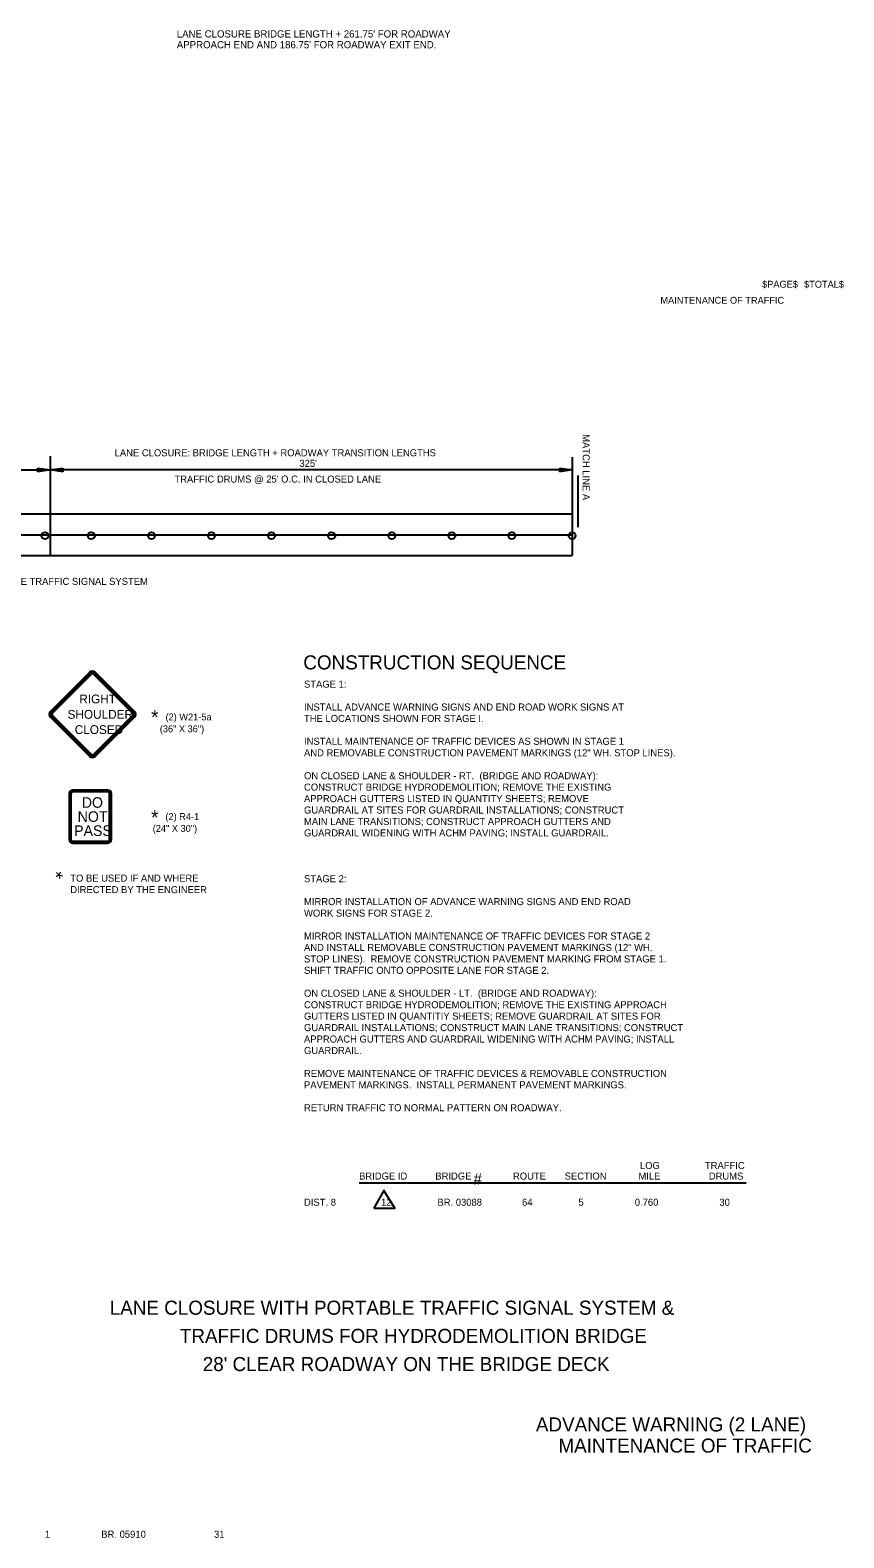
# Model space of a CAD drawing. Extents: x 1930579 to 1934718, y 596452 to 597844.
# Drawn here: x 1933176 to 1933869, y 596560 to 597843 of the extents above; entities that cross this region are included whole.
import ezdxf

# ---------------------------------------------------------------- set-up
doc = ezdxf.new("R2010")
doc.units = 0
for name, color, linetype in [('Default', 7, 'Continuous'), ('P_TC_Signs_Permanent', 7, 'Continuous'), ('P_TC_Signs_Temporary', 7, 'Continuous'), ('R_Annotation', 7, 'Continuous'), ('R_Border', 7, 'Continuous')]:
    doc.layers.add(name, color=color, linetype=linetype)

msp = doc.modelspace()

# ---------------------------------------------------------------- linework, layer by layer
at = {"layer": 'Default'}
for p, q in [((1933193.1, 597480.5), (1933193.1, 597418.7)), ((1933637.5, 597479.8), (1933637.5, 597395.9)), ((1933119.2, 597468.9), (1933193.1, 597468.9)), ((1933182.6, 597467.4), (1933182.6, 597470.5)), ((1933182.6, 597470.5), (1933193.1, 597468.9)), ((1933193.1, 597468.9), (1933182.6, 597467.4)), ((1933193.1, 597468.9), (1933203.7, 597470.5)), ((1933203.7, 597467.4), (1933193.1, 597468.9)), ((1933637.5, 597468.9), (1933193.1, 597468.9)), ((1933203.7, 597470.5), (1933203.7, 597467.4)), ((1933627, 597467.4), (1933627, 597470.5)), ((1933627, 597470.5), (1933637.5, 597468.9)), ((1933637.5, 597468.9), (1933627, 597467.4)), ((1933642.2, 597464.1), (1933642.2, 597420.1)), ((1933193.1, 597447.9), (1933193.1, 597395.6)), ((1932535.5, 597431.5), (1933637.5, 597431.5)), ((1932443.4, 597413.7), (1933637.5, 597413.7)), ((1932535.5, 597395.9), (1933637.5, 597395.9))]:
    msp.add_line(p, q, dxfattribs=at)
for centre in [(1933188.6, 597412.9), (1933228, 597412.9), (1933279.2, 597412.9), (1933330.3, 597412.9), (1933381.5, 597412.9), (1933432.6, 597412.9), (1933483.8, 597412.9), (1933535, 597412.9), (1933586.1, 597412.9), (1933637.3, 597412.9)]:
    msp.add_circle(centre, 2.88, dxfattribs=at)
at = {"layer": 'P_TC_Signs_Permanent'}
for p, q in [((1933242.1, 597196.2), (1933212.1, 597196.2)), ((1933209.1, 597193.2), (1933209.1, 597154.2)), ((1933209.7, 597193.2), (1933209.7, 597154.2)), ((1933210.6, 597193.2), (1933210.6, 597154.2)), ((1933242.1, 597195.6), (1933212.1, 597195.6)), ((1933242.1, 597194.7), (1933212.1, 597194.7)), ((1933243.6, 597154.2), (1933243.6, 597193.2)), ((1933244.5, 597154.2), (1933244.5, 597193.2)), ((1933245.1, 597154.2), (1933245.1, 597193.2)), ((1933212.1, 597152.7), (1933242.1, 597152.7)), ((1933212.1, 597151.8), (1933242.1, 597151.8)), ((1933212.1, 597151.2), (1933242.1, 597151.2))]:
    msp.add_line(p, q, dxfattribs=at)
for centre, radius, start, end in [((1933212.1, 597193.2), 3, 90, 180), ((1933242.1, 597193.2), 3, 360, 90), ((1933212.1, 597193.2), 2.4, 90, 180), ((1933212.1, 597193.2), 1.5, 90, 180), ((1933242.1, 597193.2), 2.4, 360, 90), ((1933242.1, 597193.2), 1.5, 360, 90), ((1933212.1, 597154.2), 3, 180, 270), ((1933212.1, 597154.2), 2.4, 180, 270), ((1933212.1, 597154.2), 1.5, 180, 270), ((1933242.1, 597154.2), 3, 270, 360), ((1933242.1, 597154.2), 2.4, 270, 360), ((1933242.1, 597154.2), 1.5, 270, 360)]:
    msp.add_arc(centre, radius, start, end, dxfattribs=at)
at = {"layer": 'P_TC_Signs_Temporary'}
for p, q in [((1933193.2, 597263.1), (1933226.7, 597296.6)), ((1933193.9, 597262.5), (1933227.3, 597295.9)), ((1933194.8, 597261.6), (1933228.2, 597295)), ((1933229.8, 597295), (1933263.3, 597261.6)), ((1933230.8, 597295.9), (1933264.2, 597262.5)), ((1933231.4, 597296.6), (1933264.8, 597263.1)), ((1933226.7, 597225), (1933193.2, 597258.4)), ((1933227.3, 597225.6), (1933193.9, 597259)), ((1933228.2, 597226.5), (1933194.8, 597260)), ((1933263.3, 597260), (1933229.8, 597226.5)), ((1933264.2, 597259), (1933230.8, 597225.6)), ((1933264.8, 597258.4), (1933231.4, 597225))]:
    msp.add_line(p, q, dxfattribs=at)
for centre, radius, start, end in [((1933229, 597294.2), 3.38, 45, 135), ((1933229, 597294.2), 2.44, 45, 135), ((1933229, 597294.2), 1.13, 45, 135), ((1933195.6, 597260.8), 3.37, 135, 225), ((1933195.6, 597260.8), 2.44, 135, 225), ((1933195.6, 597260.8), 1.12, 135, 225), ((1933262.5, 597260.8), 1.12, 315, 45), ((1933262.5, 597260.8), 2.44, 315, 45), ((1933262.5, 597260.8), 3.37, 315, 45), ((1933229, 597227.3), 3.38, 225, 315), ((1933229, 597227.3), 2.44, 225, 315), ((1933229, 597227.3), 1.13, 225, 315)]:
    msp.add_arc(centre, radius, start, end, dxfattribs=at)
at = {"layer": 'R_Annotation'}
msp.add_line((1933456, 596861.9), (1933785.4, 596861.9), dxfattribs=at)
msp.add_lwpolyline([(1933468.5, 596840.3), (1933486.5, 596840.3), (1933477.1, 596855.2)], close=True, dxfattribs=at)

# ---------------------------------------------------------------- texts
at = {"layer": 'Default'}
for s, height, rotation, p in [("LANE CLOSURE BRIDGE LENGTH + 261.75' FOR ROADWAY ", 6.14, 360, (1933300.8, 597837.1)), ("APPROACH END AND 186.75' FOR ROADWAY EXIT END.", 6.14, 360, (1933300.8, 597827.9)), ('MATCH LINE A', 6, 270, (1933646.3, 597499.3)), ('LANE CLOSURE: BRIDGE LENGTH + ROADWAY TRANSITION LENGTHS', 6, 360, (1933247.9, 597480.5)), ("325'", 6, 360, (1933405.2, 597471.5)), ("TRAFFIC DRUMS @ 25' O.C. IN CLOSED LANE", 6, 360, (1933298.8, 597458.1)), ('PORTABLE TRAFFIC SIGNAL SYSTEM', 6, 360, (1933130.4, 597371)), ('LANE CLOSURE WITH PORTABLE TRAFFIC SIGNAL SYSTEM &', 12, 360, (1933243.7, 596749.5)), ('TRAFFIC DRUMS FOR HYDRODEMOLITION BRIDGE', 12, 360, (1933303.4, 596725.5)), ("28' CLEAR ROADWAY ON THE BRIDGE DECK", 12, 360, (1933322.9, 596701.5))]:
    msp.add_text(s, height=height, rotation=rotation, dxfattribs=at).set_placement(p)
at = {"layer": 'P_TC_Signs_Permanent'}
for s, rotation, p in [('DO', 360, (1933219.9, 597181.2)), ('NOT', 359.9596, (1933216.4, 597169.2)), ('PASS', 360, (1933213.4, 597157.2))]:
    msp.add_text(s, height=9, rotation=rotation, dxfattribs=at).set_placement(p)
at = {"layer": 'P_TC_Signs_Temporary'}
for s, p in [('RIGHT', (1933217.8, 597270.1)), ('SHOULDER', (1933207.8, 597257)), ('CLOSED', (1933213.9, 597244))]:
    msp.add_text(s, height=7.5, rotation=360, dxfattribs=at).set_placement(p)
at = {"layer": 'R_Annotation'}
for s, height, rotation, p in [('CONSTRUCTION SEQUENCE', 12, 360, (1933408.5, 597299)), ('STAGE 1:', 6, 360, (1933409.1, 597283.5)), ('(2) W21-5a', 5.86, 360, (1933291.2, 597255.6)), ('THE LOCATIONS SHOWN FOR STAGE I.  ', 6, 360, (1933409.1, 597254.3)), ('INSTALL ADVANCE WARNING SIGNS AND END ROAD WORK SIGNS AT', 6, 360, (1933409.1, 597264)), ('(36" X 36")', 5.863, 360, (1933286.3, 597245.5)), ('INSTALL MAINTENANCE OF TRAFFIC DEVICES AS SHOWN IN STAGE 1', 6, 360, (1933409.1, 597234.8)), ('AND REMOVABLE CONSTRUCTION PAVEMENT MARKINGS (12" WH. STOP LINES). ', 6, 360, (1933409.1, 597225)), ('ON CLOSED LANE & SHOULDER - RT.  (BRIDGE AND ROADWAY):', 6, 360, (1933409.1, 597205.5)), ('CONSTRUCT BRIDGE HYDRODEMOLITION; REMOVE THE EXISTING', 6, 360, (1933409.1, 597195.8)), ('APPROACH GUTTERS LISTED IN QUANTITY SHEETS; REMOVE', 6, 360, (1933409.1, 597186)), ('(2) R4-1', 5.86, 360, (1933291.1, 597170.8)), ('GUARDRAIL AT SITES FOR GUARDRAIL INSTALLATIONS; CONSTRUCT', 6, 360, (1933409.1, 597176.3)), ('MAIN LANE TRANSITIONS; CONSTRUCT APPROACH GUTTERS AND', 6, 360, (1933409.1, 597166.5)), ('(24" X 30")', 5.863, 360, (1933280.3, 597160.7)), ('GUARDRAIL WIDENING WITH ACHM PAVING; INSTALL GUARDRAIL. ', 6, 360, (1933409.1, 597156.8)), ('*', 12, 45, (1933204.6, 597115.4)), ('TO BE USED IF AND WHERE', 6, 360, (1933210.1, 597118.3)), ('STAGE 2:', 6, 360, (1933409.1, 597117.8)), ('DIRECTED BY THE ENGINEER', 6, 360, (1933210.1, 597108.5)), ('WORK SIGNS FOR STAGE 2.  ', 6, 360, (1933409.1, 597088.5)), ('MIRROR INSTALLATION OF ADVANCE WARNING SIGNS AND END ROAD', 6, 360, (1933409.1, 597098.3)), ('MIRROR INSTALLATION MAINTENANCE OF TRAFFIC DEVICES FOR STAGE 2', 6, 360, (1933409.1, 597069)), ('AND INSTALL REMOVABLE CONSTRUCTION PAVEMENT MARKINGS (12" WH. ', 6, 360, (1933409.1, 597059.3)), ('STOP LINES).  REMOVE CONSTRUCTION PAVEMENT MARKING FROM STAGE 1.', 6, 360, (1933409.1, 597049.5)), ('SHIFT TRAFFIC ONTO OPPOSITE LANE FOR STAGE 2.', 6, 360, (1933409.1, 597039.8)), ('ON CLOSED LANE & SHOULDER - LT.  (BRIDGE AND ROADWAY):', 6, 360, (1933409.1, 597020.3)), ('CONSTRUCT BRIDGE HYDRODEMOLITION; REMOVE THE EXISTING APPROACH', 6, 360, (1933409.1, 597010.5)), ('GUTTERS LISTED IN QUANTITIY SHEETS; REMOVE GUARDRAIL AT SITES FOR', 6, 360, (1933409.1, 597000.8)), ('GUARDRAIL INSTALLATIONS; CONSTRUCT MAIN LANE TRANSITIONS; CONSTRUCT', 6, 360, (1933409.1, 596991)), ('APPROACH GUTTERS AND GUARDRAIL WIDENING WITH ACHM PAVING; INSTALL', 6, 360, (1933409.1, 596981.3)), ('GUARDRAIL.', 6, 360, (1933409.1, 596971.5)), ('REMOVE MAINTENANCE OF TRAFFIC DEVICES & REMOVABLE CONSTRUCTION', 6, 360, (1933409.1, 596952)), ('PAVEMENT MARKINGS.  INSTALL PERMANENT PAVEMENT MARKINGS.', 6, 360, (1933409.1, 596942.3)), ('RETURN TRAFFIC TO NORMAL PATTERN ON ROADWAY. ', 6, 360, (1933409.1, 596922.8)), ('LOG', 6, 360, (1933695.1, 596873.6)), ('TRAFFIC', 6, 360, (1933750.4, 596873.6)), ('BRIDGE ID', 6, 360, (1933456, 596864.6)), ('BRIDGE ', 6, 360, (1933520.9, 596864.6)), ('#', 9.6, 360, (1933553.4, 596860.4)), ('ROUTE', 6, 360, (1933587, 596864.6)), ('SECTION', 6, 360, (1933631, 596864.6)), ('MILE', 6, 360, (1933693.8, 596864.6)), ('DRUMS', 6, 360, (1933753.7, 596864.6)), ('DIST. 8', 6, 360, (1933409.1, 596842.3)), ('12', 6, 360, (1933474.7, 596842.3)), ('BR. 03088', 6, 360, (1933522.7, 596842.3)), ('64', 6, 360, (1933594.7, 596842.3)), ('5', 6, 360, (1933642.7, 596842.3)), ('0.760', 6, 360, (1933690.7, 596842.3)), ('30', 6, 360, (1933762.7, 596842.3)), ('ADVANCE WARNING (2 LANE)', 12, 360, (1933606.5, 596650.1)), ('MAINTENANCE OF TRAFFIC', 12, 360, (1933625.7, 596632.1)), ('1', 6, 360, (1933188.5, 596559.6)), ('BR. 05910', 6, 360, (1933236.5, 596559.6)), ('31', 6, 360, (1933332.5, 596559.6))]:
    msp.add_text(s, height=height, rotation=rotation, dxfattribs=at).set_placement(p)
at = {"layer": 'R_Border'}
for s, height, p in [('$PAGE$', 5.86, (1933799.1, 597624.1)), ('$TOTAL$', 5.86, (1933834.8, 597624.1)), ('MAINTENANCE OF TRAFFIC', 5.862, (1933712.5, 597610.4)), ('MAINTENANCE OF TRAFFIC', 5.862, (1933712.5, 597610.4)), ('*', 12, (1933278.9, 597252.4)), ('*', 12, (1933278.9, 597167))]:
    msp.add_text(s, height=height, rotation=360, dxfattribs=at).set_placement(p)

doc.saveas('drawing.dxf')
